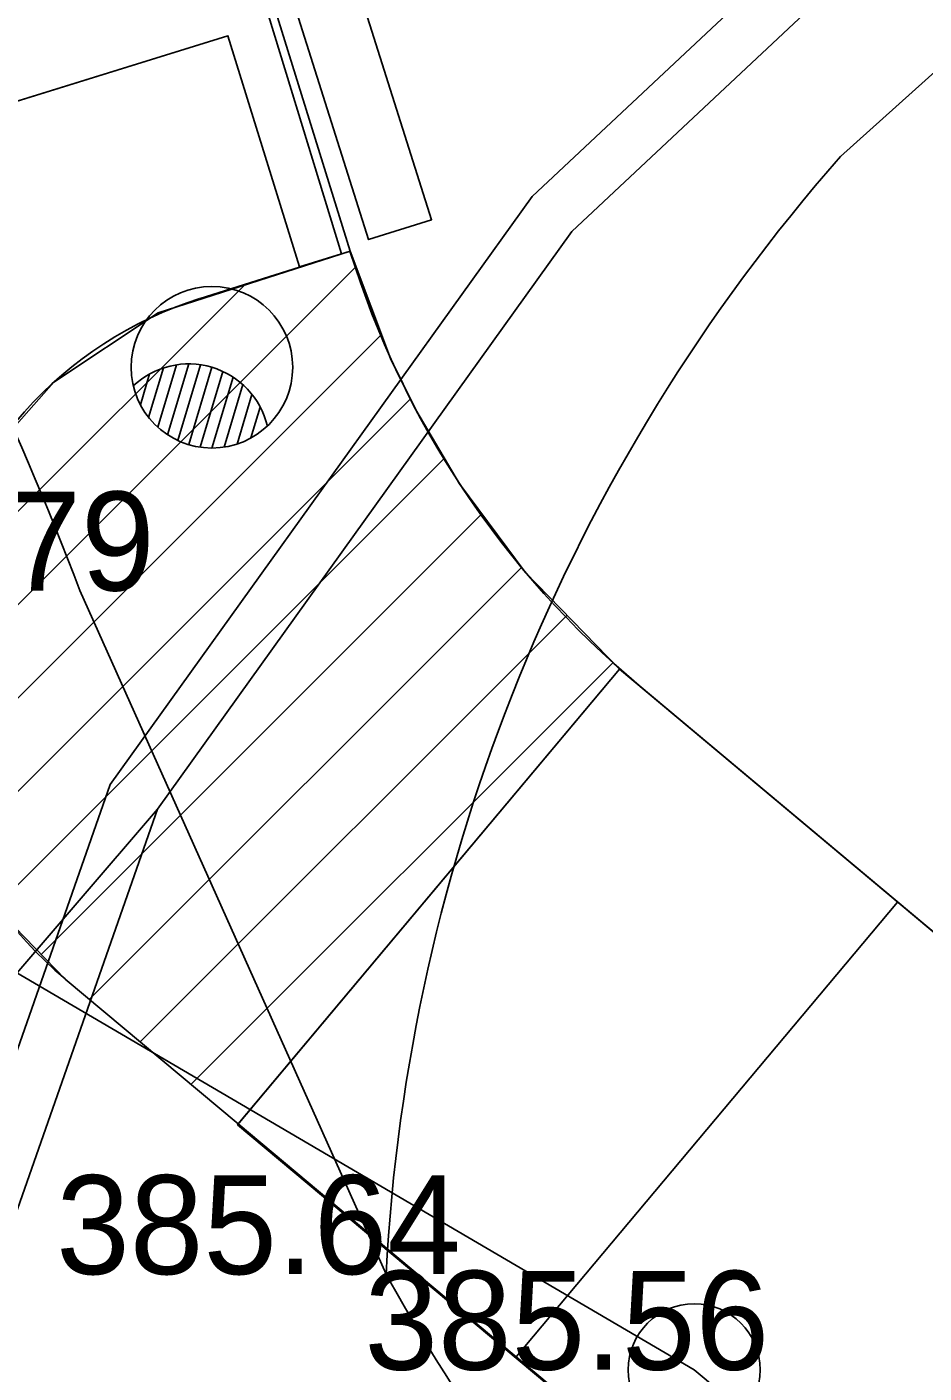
# Model space of a CAD drawing. Extents: x -438233 to -437334, y -1133133 to -1132623.
# Drawn here: x -438120.25 to -438113.45, y -1132972.08 to -1132961.87 of the extents above; entities that cross this region are included whole.
import ezdxf

# ---------------------------------------------------------------- set-up
doc = ezdxf.new("R2010")
doc.units = 0
for name, color, linetype in [('EL3', 7, 'Continuous'), ('Vrstva 1', 7, 'Continuous'), ('Vrstva 10', 7, 'Continuous'), ('Vrstva 15', 7, 'Continuous'), ('Vrstva 27', 7, 'Continuous'), ('Vrstva 3', 7, 'Continuous'), ('Vrstva 40', 7, 'Continuous'), ('Vrstva 50', 7, 'Continuous'), ('Vrstva 52', 7, 'Continuous'), ('Vrstva 53', 7, 'Continuous'), ('Vrstva 55', 7, 'Continuous')]:
    doc.layers.add(name, color=color, linetype=linetype)

# ---------------------------------------------------------------- blocks, each defined once
blk = doc.blocks.new('ELJL31_2_1')
at = {"layer": 'EL3'}
for p, q in [((10.50516, 25), (24.4949, 25)), ((6.27724, 20), (28.72281, 20)), ((3.37727, 15), (31.62278, 15)), ((1.45902, 10), (33.54102, 10)), ((0, 0), (35, 0)), ((0.35902, 5), (34.64102, 5)), ((0.35902, -5), (34.64102, -5)), ((1.45902, -10), (33.54102, -10)), ((3.37727, -15), (31.62278, -15)), ((6.27724, -20), (28.72281, -20)), ((10.50516, -25), (24.4949, -25))]:
    blk.add_line(p, q, dxfattribs=at)
blk.add_circle((0, 0), 35, dxfattribs=at)
blk.add_arc((35, 0), 34.99996, 119.999947, 239.999954, dxfattribs=at)

msp = doc.modelspace()

# ---------------------------------------------------------------- linework, layer by layer
at = {"layer": 'Vrstva 1'}
for p, q in [((-438118.983, -1132959.758), (-438117.801, -1132963.571)), ((-438117.801, -1132963.571), (-438118.938, -1132963.931)), ((-438119.849, -1132966.145), (-438119.849, -1132966.145)), ((-438115.759, -1132966.741), (-438118.649, -1132970.19)), ((-438115.61, -1132966.865), (-438098.33, -1132981.342)), ((-438150.612, -1133004.31), (-438119.26, -1132967.803)), ((-438113.651, -1132968.507), (-438116.541, -1132971.956)), ((-438119.96, -1132969.091), (-438118.649, -1132970.19)), ((-438118.649, -1132970.19), (-438104.276, -1132982.231)), ((-438117.528, -1132971.329), (-438117.528, -1132971.329)), ((-438115.192, -1132972.054), (-438115.192, -1132972.054))]:
    msp.add_line(p, q, dxfattribs=at)
msp.add_arc((-438111.115, -1132961.499), 7, 197.2179, 230.0448, dxfattribs=at)
at = {"layer": 'Vrstva 10'}
msp.add_line((-438095.924, -1132946.534), (-438114.084, -1132962.853), dxfattribs=at)
msp.add_lwpolyline([(-438117.528, -1132971.329), (-438119.849, -1132966.145)], dxfattribs=at)
for centre, radius, start, end in [((-438138.638, -1132973.144), 20.05, 20.4315, 44.1439), ((-438103.579, -1132972.06), 13.968, 138.77, 177.0017), ((-438101.59, -1132962.409), 18.265, 209.2336, 224.3246)]:
    msp.add_arc(centre, radius, start, end, dxfattribs=at)
at = {"layer": 'Vrstva 15'}
for p, q in [((-438118.726, -1132961.938), (-438122.233, -1132963.025)), ((-438118.726, -1132961.938), (-438118.183, -1132963.691)), ((-438117.866, -1132963.592), (-438118.183, -1132963.691))]:
    msp.add_line(p, q, dxfattribs=at)
msp.add_lwpolyline([(-438119.057, -1132959.694), (-438119.389, -1132959.798), (-438118.963, -1132961.174), (-438122.47, -1132962.261), (-438122.233, -1132963.025), (-438118.726, -1132961.938), (-438118.183, -1132963.691), (-438117.866, -1132963.592)], close=True, dxfattribs=at)
at = {"layer": 'Vrstva 27'}
msp.add_circle((-438115.192, -1132972.054), 0.5, dxfattribs=at)
at = {"layer": 'Vrstva 40'}
for p, q in [((-438121.01, -1132966.944), (-438117.756, -1132963.69)), ((-438120.971, -1132966.198), (-438118.602, -1132963.829)), ((-438120.917, -1132967.558), (-438117.563, -1132964.203)), ((-438120.053, -1132964.572), (-438120.043, -1132964.562)), ((-438120.691, -1132968.039), (-438117.343, -1132964.691)), ((-438120.465, -1132968.52), (-438117.086, -1132965.141)), ((-438120.142, -1132968.904), (-438116.802, -1132965.564)), ((-438119.776, -1132969.245), (-438116.501, -1132965.97)), ((-438119.391, -1132969.568), (-438116.156, -1132966.333)), ((-438119.007, -1132969.89), (-438115.807, -1132966.691))]:
    msp.add_line(p, q, dxfattribs=at)
msp.add_lwpolyline([(-438117.801, -1132963.571), (-438119.254, -1132964.038), (-438120.046, -1132964.564), (-438120.483, -1132965.058), (-438120.957, -1132966.078), (-438121.035, -1132966.732), (-438120.945, -1132967.499), (-438120.418, -1132968.62), (-438119.96, -1132969.091), (-438118.649, -1132970.19), (-438115.759, -1132966.741), (-438116.473, -1132966.007), (-438116.971, -1132965.337), (-438117.302, -1132964.775), (-438117.494, -1132964.385)], close=True, dxfattribs=at)
at = {"layer": 'Vrstva 50'}
for points in [[(-438118.864, -1132959.677), (-438118.387, -1132959.526), (-438117.183, -1132963.333), (-438117.66, -1132963.484)], [(-438115.759, -1132966.741), (-438101.366, -1132978.798), (-438104.261, -1132982.253), (-438118.653, -1132970.196)]]:
    msp.add_lwpolyline(points, close=True, dxfattribs=at)
msp.add_arc((-438118.034, -1132966.791), 3, 107.5443, 230.0448, dxfattribs=at)
at = {"layer": 'Vrstva 52'}
for points in [[(-438128.855, -1132990.779), (-438128.856, -1132990.91), (-438128.989, -1132990.91), (-438128.989, -1132990.659), (-438128.93, -1132990.596), (-438129.59, -1132987.39), (-438128.59, -1132984.69), (-438123.607, -1132978.703), (-438122.927, -1132977.811), (-438122.184, -1132976.902), (-438122.789, -1132976.078), (-438121.848, -1132973.845), (-438121.368, -1132972.611), (-438119.619, -1132967.617), (-438116.421, -1132963.158), (-438109.667, -1132956.824), (-438099.67, -1132947.487), (-438095.701, -1132943.378), (-438089.916, -1132937.924), (-438083.958, -1132932.455), (-438080.074, -1132928.641), (-438079.488, -1132927.786), (-438078.793, -1132926.015), (-438077.623, -1132919.546)], [(-438077.217, -1132919.546), (-438078.406, -1132926.125), (-438079.132, -1132927.975), (-438079.766, -1132928.899), (-438083.683, -1132932.745), (-438089.644, -1132938.217), (-438095.42, -1132943.663), (-438099.389, -1132947.772), (-438109.394, -1132957.116), (-438116.119, -1132963.423), (-438119.26, -1132967.803), (-438120.993, -1132972.75), (-438122.088, -1132975.591), (-438122.213, -1132976.074), (-438122.355, -1132976.074), (-438122.355, -1132975.945)]]:
    msp.add_lwpolyline(points, dxfattribs=at)
at = {"layer": 'Vrstva 55'}
msp.add_lwpolyline([(-438074.959, -1133013.61), (-438076.856, -1133009.846), (-438083.298, -1132998.719), (-438115.192, -1132972.054), (-438146.469, -1132953.711), (-438176.9, -1132931.48)], dxfattribs=at)

# ---------------------------------------------------------------- block references
at = {"layer": 'Vrstva 53', "xscale": 0.0175, "yscale": 0.0175, "rotation": -106.66592339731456}
msp.add_blockref('ELJL31_2_1', (-438118.848, -1132964.452), dxfattribs=at)

# ---------------------------------------------------------------- texts
at = {"layer": 'Vrstva 3'}
for s, p in [('385.79 ', (-438122.349, -1132966.145)), ('385.64 ', (-438120.028, -1132971.329)), ('385.56 ', (-438117.692, -1132972.054))]:
    msp.add_text(s, height=0.75, dxfattribs=at).set_placement(p)

doc.saveas('drawing.dxf')
